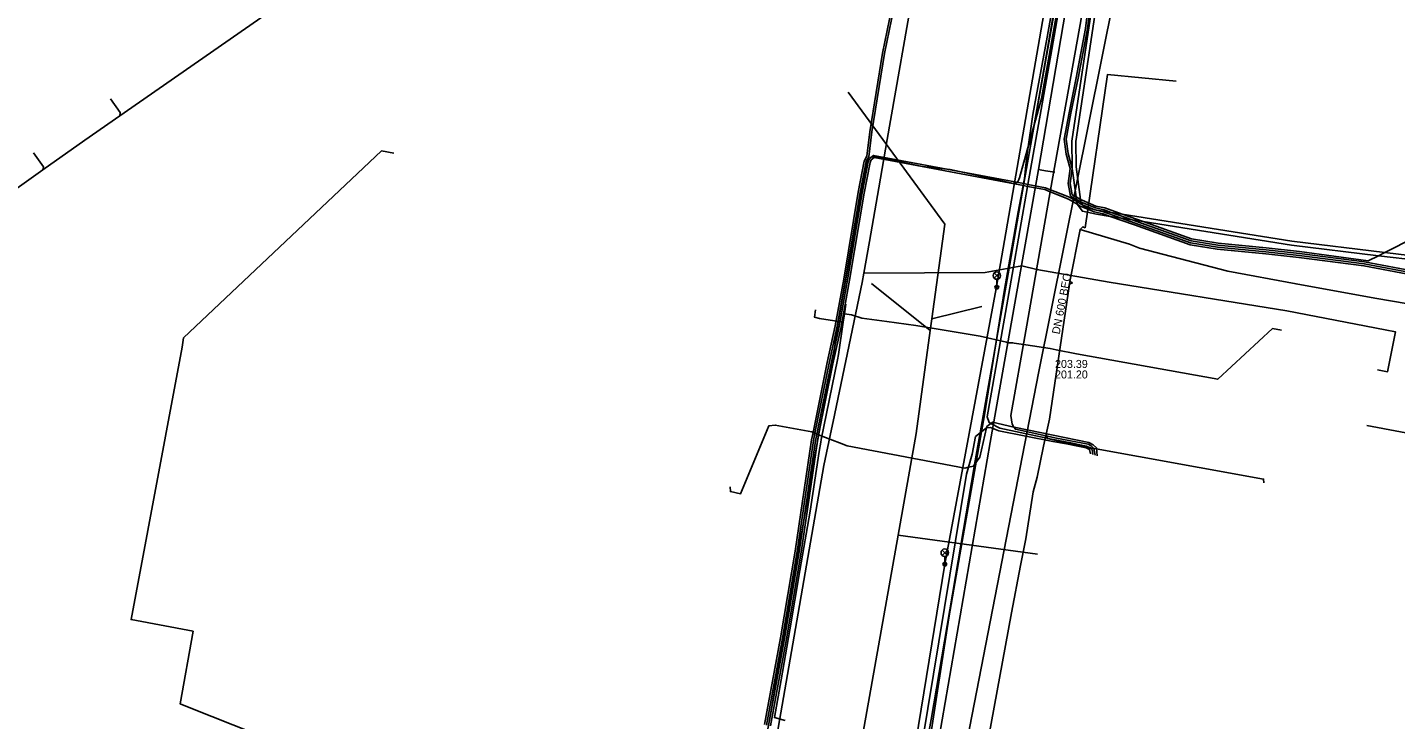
# Model space of a CAD drawing. Extents: x -596228 to -595156, y -1161235 to -1159373.
# Drawn here: x -595977.9 to -595841.1, y -1160214.5 to -1160145.3 of the extents above; entities that cross this region are included whole.
import ezdxf

# ---------------------------------------------------------------- set-up
doc = ezdxf.new("R2010")
doc.units = 0
for name, color, linetype in [('Vrstva 1', 7, 'Continuous'), ('Vrstva 12', 7, 'Continuous'), ('Vrstva 14', 7, 'Continuous'), ('Vrstva 19', 7, 'Continuous'), ('Vrstva 33', 7, 'Continuous'), ('Vrstva 37', 7, 'Continuous'), ('Vrstva 4', 7, 'Continuous'), ('Vrstva 42', 7, 'Continuous'), ('Vrstva 44', 7, 'Continuous'), ('Vrstva 53', 7, 'Continuous'), ('Vrstva 55', 7, 'Continuous'), ('Vrstva 58', 7, 'Continuous'), ('Vrstva 9', 7, 'Continuous')]:
    doc.layers.add(name, color=color, linetype=linetype)

msp = doc.modelspace()

# ---------------------------------------------------------------- linework, layer by layer
at = {"layer": 'Vrstva 1'}
for p, q in [((-595867.89, -1160135.48), (-595876.82, -1160179.87)), ((-595893.5, -1160170.94), (-595887.641, -1160175.628)), ((-595882.49, -1160173.22), (-595887.478, -1160174.449)), ((-595876.82, -1160179.87), (-595885.54, -1160224.74))]:
    msp.add_line(p, q, dxfattribs=at)
for points in [[(-595937, -1160132.13), (-595950.198, -1160141.308), (-595968.675, -1160154.158), (-595972.17, -1160156.6)], [(-595972.17, -1160156.6), (-595976.352, -1160159.563), (-595981.746, -1160163.395), (-595988.272, -1160168.027), (-595996.548, -1160173.9), (-596006.2, -1160180.75)]]:
    msp.add_lwpolyline(points, dxfattribs=at)
at = {"layer": 'Vrstva 12'}
for p, q in [((-595893.73, -1160166.74), (-595894.28, -1160169.9)), ((-595869.76, -1160170.8), (-595876.98, -1160169.52))]:
    msp.add_line(p, q, dxfattribs=at)
for points in [[(-595873.83, -1160048.21), (-595874.58, -1160057.28), (-595878.97, -1160081.97), (-595886.34, -1160124.44), (-595887.99, -1160133.91), (-595889.12, -1160140.39), (-595891.94, -1160156.53), (-595892.78, -1160161.36), (-595893.73, -1160166.74)], [(-595894.28, -1160169.9), (-595894.44, -1160170.83), (-595896.08, -1160178.64), (-595897.36, -1160184.72)], [(-595876.98, -1160169.52), (-595878.47, -1160169.15), (-595882.15, -1160169.82), (-595894.28, -1160169.9)], [(-595842.94, -1160179.55), (-595841.91, -1160179.74), (-595841.14, -1160175.74), (-595842.17, -1160175.54), (-595851.99, -1160173.67), (-595869.76, -1160170.8)], [(-595961.32, -1160205.66), (-595967.538, -1160204.493), (-595962.433, -1160177.292)], [(-595897.36, -1160184.72), (-595897.52, -1160185.49), (-595898.28, -1160189.11), (-595902.98, -1160216.12), (-595905.04, -1160227.87), (-595904.75, -1160229.39)], [(-595906.85, -1160231.25), (-595907.387, -1160230.78), (-595907.31, -1160230.14), (-595906.92, -1160227.97), (-595939.63, -1160222.04), (-595961.4, -1160213.41), (-595962.62, -1160212.93), (-595961.32, -1160205.66)]]:
    msp.add_lwpolyline(points, dxfattribs=at)
at = {"layer": 'Vrstva 14'}
for points in [[(-595903.525, -1160327.591), (-595903.438, -1160327.11), (-595895.992, -1160276.218), (-595895.362, -1160271.913), (-595894.416, -1160266.829), (-595893.077, -1160257.958), (-595892.847, -1160256.335), (-595887.94, -1160223.167), (-595881.65, -1160186.81), (-595876.814, -1160159.541), (-595869.649, -1160117.522), (-595863.209, -1160078.856), (-595858.091, -1160048.124), (-595857.576, -1160045.207), (-595855.994, -1160045.422), (-595855.543, -1160042.523), (-595857.05, -1160042.292), (-595850.5, -1160006.311), (-595840.026, -1160007.969)], [(-595962.433, -1160177.292), (-595962.288, -1160176.345), (-595942.49, -1160157.676), (-595941.286, -1160157.903)], [(-595876.814, -1160159.541), (-595876.665, -1160159.568), (-595876.11, -1160159.663), (-595875.188, -1160159.817)]]:
    msp.add_lwpolyline(points, dxfattribs=at)
at = {"layer": 'Vrstva 19'}
msp.add_line((-595853.424, -1160175.421), (-595852.529, -1160175.575), dxfattribs=at)
for points in [[(-595896.066, -1160172.979), (-595896.214, -1160173.968), (-595896.337, -1160174.778), (-595896.826, -1160178.03), (-595896.901, -1160178.556), (-595898.533, -1160186.498), (-595898.585, -1160186.778), (-595898.735, -1160187.701), (-595899.64, -1160193.681), (-595900.679, -1160199.583), (-595901.683, -1160205.513), (-595902.544, -1160210.536), (-595903.221, -1160214.288), (-595902.141, -1160214.568)], [(-595896.337, -1160174.778), (-595898.698, -1160174.423), (-595899.202, -1160174.302), (-595899.124, -1160173.544)], [(-595853.424, -1160175.421), (-595858.892, -1160180.49), (-595873.012, -1160177.94), (-595875.042, -1160177.553), (-595875.663, -1160177.434), (-595878.092, -1160177.063), (-595879.267, -1160176.879), (-595879.392, -1160176.849), (-595879.878, -1160176.852), (-595879.906, -1160176.844), (-595880.016, -1160176.773), (-595882.664, -1160176.181), (-595886.045, -1160175.635), (-595889.092, -1160175.129), (-595891.975, -1160174.707), (-595894.471, -1160174.374), (-595895.502, -1160174.05), (-595896.214, -1160173.968)]]:
    msp.add_lwpolyline(points, dxfattribs=at)
at = {"layer": 'Vrstva 33'}
for p, q in [((-595881.245, -1160169.865), (-595880.715, -1160170.395)), ((-595881.245, -1160170.395), (-595880.715, -1160169.865)), ((-595880.98, -1160171.28), (-595880.98, -1160170.505)), ((-595886.455, -1160197.555), (-595885.925, -1160198.085)), ((-595886.455, -1160198.085), (-595885.925, -1160197.555)), ((-595886.19, -1160198.97), (-595886.19, -1160198.195))]:
    msp.add_line(p, q, dxfattribs=at)
for centre, radius in [((-595880.98, -1160170.13), 0.375), ((-595880.98, -1160171.28), 0.19), ((-595880.98, -1160171.28), 0.05), ((-595886.19, -1160197.82), 0.375), ((-595886.19, -1160198.97), 0.19), ((-595886.19, -1160198.97), 0.05)]:
    msp.add_circle(centre, radius, dxfattribs=at)
at = {"layer": 'Vrstva 37'}
msp.add_lwpolyline([(-595820.693, -1160183.988), (-595827.936, -1160182.62), (-595828.926, -1160187.943), (-595843.992, -1160185.1)], dxfattribs=at)
at = {"layer": 'Vrstva 42'}
for points in [[(-595899.339, -1160297.503), (-595902.099, -1160297.56), (-595902.383, -1160297.165), (-595902.586, -1160296.883), (-595902.568, -1160296.769), (-595901.316, -1160288.727), (-595900.471, -1160287.553), (-595898.687, -1160276.707), (-595898.101, -1160273.351), (-595895.17, -1160256.55), (-595893.577, -1160246.717), (-595892.781, -1160243.14), (-595887.556, -1160214.494), (-595883.249, -1160189.231), (-595883.208, -1160189), (-595882.655, -1160185.86), (-595879.849, -1160169.95), (-595878.786, -1160163.811), (-595878.313, -1160161.147), (-595878.278, -1160160.95), (-595875.884, -1160147.461), (-595871.512, -1160122.724)], [(-595837.329, -1160168.604), (-595838.64, -1160168.248), (-595842.189, -1160167.823), (-595851.48, -1160166.71), (-595868.445, -1160164), (-595869.541, -1160163.825), (-595870.937, -1160163.602), (-595871.268, -1160163.534), (-595872.199, -1160163.341), (-595872.405, -1160163.064), (-595872.577, -1160162.834), (-595872.586, -1160162.768), (-595872.619, -1160162.52), (-595873.058, -1160159.275), (-595873.094, -1160156.721), (-595869.968, -1160135.891), (-595869.795, -1160135.333), (-595869.636, -1160134.237)], [(-595871.373, -1160188.013), (-595871.451, -1160187.525), (-595871.706, -1160187.303), (-595872.016, -1160187.159), (-595872.505, -1160187.059), (-595873.57, -1160186.859), (-595875.511, -1160186.471), (-595880.68, -1160185.372), (-595881.573, -1160184.907), (-595881.735, -1160184.823), (-595881.964, -1160184.246), (-595879.455, -1160170.019), (-595877.904, -1160161.223), (-595877.869, -1160161.026), (-595875.49, -1160147.531), (-595873.416, -1160135.703)], [(-595871.165, -1160188.086), (-595871.28, -1160187.402), (-595871.55, -1160187.132), (-595871.837, -1160186.966), (-595875.017, -1160186.367), (-595879.118, -1160185.492), (-595879.274, -1160185.263), (-595879.464, -1160184.985), (-595879.597, -1160184.104), (-595878.098, -1160175.645), (-595875.64, -1160161.758), (-595875.604, -1160161.557), (-595874.688, -1160156.38), (-595870.992, -1160135.708)], [(-595838.716, -1160168.642), (-595842.831, -1160168.149), (-595851.536, -1160167.106), (-595866.367, -1160164.737), (-595867.447, -1160164.565), (-595868.542, -1160164.39), (-595869.638, -1160164.215), (-595871.009, -1160163.996), (-595872.429, -1160163.701), (-595872.944, -1160163.01), (-595872.959, -1160162.99), (-595872.992, -1160162.747), (-595873.022, -1160162.522), (-595873.056, -1160162.273), (-595873.439, -1160159.443), (-595873.443, -1160159.415), (-595873.458, -1160159.305), (-595873.494, -1160156.693), (-595870.36, -1160135.801)], [(-595830.08, -1160171.424), (-595844.214, -1160168.761), (-595850.738, -1160167.921), (-595854.06, -1160167.561), (-595858.887, -1160167.081), (-595861.555, -1160166.673), (-595867.076, -1160164.696), (-595867.447, -1160164.565), (-595869.541, -1160163.825), (-595870.252, -1160163.574), (-595871.13, -1160163.374), (-595872.552, -1160162.787), (-595872.586, -1160162.768), (-595873.022, -1160162.522), (-595873.616, -1160162.186), (-595873.851, -1160160.922), (-595873.642, -1160159.447), (-595874.048, -1160157.991), (-595874.261, -1160156.508), (-595873.768, -1160153.871), (-595873.038, -1160150.361), (-595872.109, -1160145.435), (-595871.299, -1160138.535)], [(-595871.101, -1160138.565), (-595871.911, -1160145.465), (-595872.842, -1160150.399), (-595873.572, -1160153.909), (-595874.059, -1160156.512), (-595873.852, -1160157.949), (-595873.443, -1160159.415), (-595873.438, -1160159.433), (-595873.439, -1160159.443), (-595873.649, -1160160.918), (-595873.436, -1160162.059), (-595873.056, -1160162.273), (-595872.619, -1160162.52), (-595872.464, -1160162.607), (-595871.069, -1160163.183), (-595870.197, -1160163.381), (-595868.445, -1160164), (-595867.009, -1160164.507), (-595866.367, -1160164.737), (-595861.506, -1160166.478), (-595858.862, -1160166.882), (-595854.039, -1160167.362), (-595850.715, -1160167.722), (-595843.856, -1160168.67), (-595842.831, -1160168.149), (-595842.189, -1160167.823), (-595836.34, -1160164.85)], [(-595890.778, -1160139.94), (-595892.408, -1160147.902), (-595893.689, -1160155.756), (-595893.985, -1160158.208), (-595894.245, -1160158.694), (-595894.835, -1160161.807), (-595896.296, -1160170.489), (-595897.134, -1160175.151), (-595897.953, -1160178.828), (-595899.362, -1160185.797), (-595899.516, -1160186.559), (-595901.136, -1160197.663), (-595902.605, -1160206.328), (-595904.206, -1160214.999)], [(-595890.582, -1160139.98), (-595892.212, -1160147.938), (-595893.491, -1160155.784), (-595893.79, -1160158.261), (-595894.048, -1160158.731), (-595894.638, -1160161.842), (-595896.099, -1160170.523), (-595896.938, -1160175.19), (-595897.758, -1160178.869), (-595899.175, -1160185.884), (-595899.319, -1160186.593), (-595900.939, -1160197.694), (-595902.409, -1160206.363), (-595904.009, -1160215.033)], [(-595830.14, -1160171.616), (-595844.246, -1160168.959), (-595850.762, -1160168.119), (-595854.08, -1160167.759), (-595858.913, -1160167.279), (-595861.605, -1160166.867), (-595867.144, -1160164.884), (-595868.542, -1160164.39), (-595870.308, -1160163.766), (-595871.19, -1160163.566), (-595871.268, -1160163.534), (-595872.405, -1160163.064), (-595872.628, -1160162.973), (-595872.992, -1160162.747), (-595873.636, -1160162.347), (-595874.153, -1160162.137), (-595875.604, -1160161.557), (-595876.112, -1160161.354), (-595877.869, -1160161.026), (-595878.278, -1160160.95), (-595879.182, -1160160.782), (-595893.306, -1160158.123), (-595893.726, -1160158.449), (-595893.852, -1160158.769), (-595894.442, -1160161.878), (-595895.901, -1160170.557), (-595896.742, -1160175.23), (-595897.562, -1160178.911), (-595898.989, -1160185.971), (-595899.121, -1160186.627), (-595900.741, -1160197.726), (-595902.212, -1160206.397), (-595903.811, -1160215.067)], [(-595830.201, -1160171.808), (-595844.277, -1160169.156), (-595850.785, -1160168.318), (-595854.101, -1160167.958), (-595858.938, -1160167.478), (-595861.654, -1160167.062), (-595867.21, -1160165.073), (-595869.638, -1160164.215), (-595870.363, -1160163.959), (-595871.251, -1160163.757), (-595872.704, -1160163.158), (-595872.944, -1160163.01), (-595873.74, -1160162.521), (-595874.227, -1160162.323), (-595875.64, -1160161.758), (-595876.168, -1160161.547), (-595877.904, -1160161.223), (-595878.313, -1160161.147), (-595879.218, -1160160.978), (-595893.254, -1160158.337), (-595893.56, -1160158.574), (-595893.659, -1160158.824), (-595894.245, -1160161.913), (-595895.704, -1160170.591), (-595896.546, -1160175.269), (-595897.367, -1160178.952), (-595898.802, -1160186.054), (-595898.924, -1160186.661), (-595900.544, -1160197.757), (-595902.015, -1160206.432), (-595903.614, -1160215.101)], [(-595907.63, -1160191.23), (-595907.626, -1160191.71), (-595906.612, -1160191.942), (-595903.772, -1160185.131), (-595903.134, -1160185.073), (-595899.489, -1160185.738), (-595899.362, -1160185.797), (-595899.175, -1160185.884), (-595898.989, -1160185.971), (-595898.852, -1160186.035), (-595898.802, -1160186.054), (-595896.702, -1160186.834), (-595895.943, -1160187.142), (-595884.188, -1160189.367), (-595883.806, -1160189.275), (-595883.326, -1160189.159), (-595883.208, -1160189), (-595882.675, -1160188.282), (-595882.014, -1160185.358), (-595881.98, -1160185.209), (-595881.573, -1160184.907), (-595881.42, -1160184.793), (-595879.274, -1160185.263), (-595879.09, -1160185.303), (-595871.795, -1160186.798), (-595871.35, -1160187.058), (-595871.034, -1160187.355), (-595870.96, -1160188.125)], [(-595888.976, -1160220.051), (-595884.001, -1160189.966), (-595883.806, -1160189.275), (-595883.434, -1160187.961), (-595883.112, -1160186.219), (-595882.655, -1160185.86), (-595882.014, -1160185.358), (-595881.987, -1160185.337), (-595881.624, -1160185.31), (-595880.776, -1160185.659), (-595875.384, -1160186.712), (-595874.023, -1160186.95), (-595872.9, -1160187.171), (-595872.066, -1160187.342), (-595871.707, -1160187.51), (-595871.623, -1160187.954)]]:
    msp.add_lwpolyline(points, dxfattribs=at)
at = {"layer": 'Vrstva 44'}
for points in [[(-595877.641, -1160157.25), (-595877.206, -1160154.877), (-595875.823, -1160146.872), (-595874.194, -1160137.323), (-595870.493, -1160116.878), (-595869.152, -1160108.721), (-595866.815, -1160096.285), (-595864.579, -1160081.663), (-595862.969, -1160076.234), (-595861.913, -1160073.61), (-595860.434, -1160067.371), (-595860.472, -1160066.199), (-595860.336, -1160065.565), (-595860.108, -1160064.5), (-595859.919, -1160062.97), (-595859.588, -1160060.589), (-595859.432, -1160059.468), (-595859.081, -1160056.226), (-595858.987, -1160055.362), (-595857.892, -1160045.25)], [(-595877.88, -1160157.51), (-595877.39, -1160154.03), (-595875.94, -1160146.32), (-595874.58, -1160138.63)], [(-595896.897, -1160273.045), (-595895.909, -1160264.308), (-595894.529, -1160255.491), (-595892.955, -1160246.953), (-595891.073, -1160236.98), (-595889.376, -1160227.647), (-595886.84, -1160211.177), (-595885.783, -1160204.31), (-595884.451, -1160196.692), (-595882.21, -1160184.038), (-595880.223, -1160171.529), (-595878.837, -1160163.768), (-595878.228, -1160160.447), (-595878.1, -1160159.1), (-595877.88, -1160157.51)]]:
    msp.add_lwpolyline(points, dxfattribs=at)
at = {"layer": 'Vrstva 53'}
for points in [[(-595874.46, -1160140.81), (-595876.52, -1160152.45), (-595878.72, -1160160.38)], [(-595878.72, -1160160.38), (-595878.9, -1160160.76), (-595879.19, -1160160.96), (-595882.85, -1160160.12), (-595885.65, -1160159.55), (-595888.42, -1160159.22), (-595893.19, -1160158.25), (-595893.53, -1160158.31), (-595893.95, -1160158.7), (-595894.87, -1160163.74), (-595896.89, -1160175), (-595897.42, -1160178.86), (-595898.79, -1160185.95), (-595898.99, -1160187.07), (-595901.26, -1160200.17), (-595903.5, -1160213.4), (-595905.82, -1160226.28), (-595905.44, -1160228.74)]]:
    msp.add_lwpolyline(points, dxfattribs=at)
at = {"layer": 'Vrstva 55'}
msp.add_lwpolyline([(-595901.722, -1160303.649), (-595901.92, -1160299.12), (-595902.19, -1160291.297), (-595890.66, -1160226.32), (-595886.19, -1160198.97), (-595881.04, -1160171.41), (-595876.29, -1160143.99), (-595871.58, -1160116.92), (-595868.39, -1160099.39), (-595861.162, -1160062.826), (-595862.06, -1160062.41)], dxfattribs=at)
at = {"layer": 'Vrstva 58'}
for points in [[(-595872.66, -1160165.52), (-595872.38, -1160165.25), (-595872.16, -1160165.35), (-595869.91, -1160150.04), (-595863.054, -1160150.712)], [(-595881.84, -1160216.53), (-595879.51, -1160203.81), (-595878.61, -1160199.1), (-595878.08, -1160196.42), (-595877.34, -1160191.74), (-595876.94, -1160190.28), (-595876.32, -1160187.16), (-595876.052, -1160185.985), (-595875.71, -1160184.49), (-595873.707, -1160170.979), (-595873.67, -1160170.73), (-595872.66, -1160165.52), (-595867.73, -1160167.01), (-595866.73, -1160167.4), (-595857.9, -1160169.69), (-595851.07, -1160170.96), (-595843.19, -1160172.38), (-595829.87, -1160174.67)], [(-595873.434, -1160170.848), (-595873.67, -1160170.73), (-595872.66, -1160165.52)], [(-595872.66, -1160165.52), (-595867.73, -1160167.01), (-595866.73, -1160167.4), (-595857.9, -1160169.69), (-595851.07, -1160170.96), (-595843.19, -1160172.38), (-595829.87, -1160174.67), (-595817.38, -1160177.1), (-595816.11, -1160177.55), (-595804.45, -1160179.61), (-595795.2, -1160181.34), (-595786.31, -1160182.8)], [(-595876.052, -1160185.985), (-595875.71, -1160184.49), (-595873.707, -1160170.979), (-595873.434, -1160170.848)], [(-595881.84, -1160216.53), (-595879.51, -1160203.81), (-595878.61, -1160199.1), (-595878.08, -1160196.42), (-595877.34, -1160191.74), (-595876.94, -1160190.28), (-595876.32, -1160187.16), (-595876.052, -1160185.985)], [(-595876.052, -1160185.985), (-595875.91, -1160186.41), (-595873.24, -1160187.05), (-595854.32, -1160190.47), (-595854.301, -1160190.842)]]:
    msp.add_lwpolyline(points, dxfattribs=at)
at = {"layer": 'Vrstva 9'}
for p, q in [((-595895.84, -1160151.82), (-595886.17, -1160164.98)), ((-595876.92, -1160197.97), (-595890.86, -1160196.053))]:
    msp.add_line(p, q, dxfattribs=at)
for points in [[(-595969.586, -1160152.459), (-595968.619, -1160153.84), (-595968.677, -1160154.17)], [(-595977.285, -1160157.877), (-595976.302, -1160159.28), (-595976.353, -1160159.569)], [(-595886.17, -1160164.98), (-595887.478, -1160174.449), (-595887.641, -1160175.628), (-595889.06, -1160185.9)], [(-595889.06, -1160185.9), (-595890.86, -1160196.053), (-595895.414, -1160221.746)]]:
    msp.add_lwpolyline(points, dxfattribs=at)

# ---------------------------------------------------------------- texts
at = {"layer": 'Vrstva 4'}
msp.add_text('DN 600 BEO', height=0.8, rotation=79, dxfattribs=at).set_placement((-595874.706, -1160176.042))
for s, p in [('203.39', (-595875.165, -1160179.361)), ('201.20', (-595875.165, -1160180.411))]:
    msp.add_text(s, height=0.8, dxfattribs=at).set_placement(p)

doc.saveas('drawing.dxf')
